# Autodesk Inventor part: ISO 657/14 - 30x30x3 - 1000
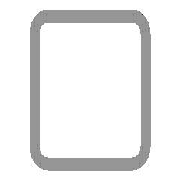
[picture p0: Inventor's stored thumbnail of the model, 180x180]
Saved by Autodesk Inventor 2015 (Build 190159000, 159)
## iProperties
IsCustomPart: 1
Created: 2014-02
Part Number: ISO 657/14 - 30x30x3 - 1000
Material: Steel, Mild
Description: Hot-rolled steel sections - part 14: hot-finished structrual hollow sections - Dimensions and sectional properties
Document SubType Name: Modeling
Standard: ISO
Designer: 徐冠倫
Standard Revision: Third edition 2000-03-15
Standards Organization: ISO
Language: en-US
Size Designation: 30x30x3
Categories: <MemberInstance><Categories><Category DisplayName="Structural Shapes" InternalName="089c4875-fa83-4c05-b084-43b9cc11f5ed" Mnemonic="GRDR"><CategoryParameter Dis
Stock Number: 30x30x3
Density: 7.85 g/cm^3
Appearance: Semi-Polished
Mass: 2422.11 g
Surface Area: 2063.16 cm^2
Volume: 308.549 cm^3
_CCFamilyMember: 8
_CCFamilyDisplayName: ISO 657/14 - 2000 (Square) - Hot-rolled steel sections - part 14: hot-finished structrual hollow sections - Dimensions and sectional properties
_FrameMemberDoc: Frame Member File
_Version: 15.0.0
_GetPNFromCC: 1
G_L: 1000.000 mm
G_W: 30.000 mm
G_H: 30.000 mm
Author: 徐冠倫
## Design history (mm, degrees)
node "Start plane"
node "End plane"
sketch "Sketch"
  geometry: L1 (-15, -10.5)-(-15, 10.5); L2 (-10.5, 15)-(10.5, 15); L3 (15, 10.5)-(15, -10.5); L4 (10.5, -15)-(-10.5, -15); L5 (-10.5, 12)-(10.5, 12); L6 (12, 10.5)-(12, -10.5); L7 (10.5, -12)-(-10.5, -12); L8 (-12, -10.5)-(-12, 10.5); L9 (0, 22.305)-(0, -22.305) reference; L10 (-22.305, 0)-(22.305, 0) reference; A1 r 4.5 centre (-10.5, -10.5) between (-15, -10.5) and (-10.5, -15); A2 r 4.5 centre (-10.5, 10.5) between (-10.5, 15) and (-15, 10.5); A3 r 4.5 centre (10.5, 10.5) between (15, 10.5) and (10.5, 15); A4 r 4.5 centre (10.5, -10.5) between (10.5, -15) and (15, -10.5); A5 r 1.5 centre (-10.5, 10.5) between (-10.5, 12) and (-12, 10.5); A6 r 1.5 centre (10.5, 10.5) between (12, 10.5) and (10.5, 12); A7 r 1.5 centre (10.5, -10.5) between (10.5, -12) and (12, -10.5); A8 r 1.5 centre (-10.5, -10.5) between (-12, -10.5) and (-10.5, -12)
  constraints: 16 end point, 16 point on circle, 8 centre point, 8 tangent, 4 parallel, 3 equal radius, 2 perpendicular, 7 other
  dimensions: "d7" = 4.5 radius of A1 (= G_IR); "d10" = 30 distance between parallel lines of L2 L4 (= G_H); "d11" = 30 distance between parallel lines of L1 L3 (= G_W); "d12" = 3 distance between parallel lines of L3 L6 (= G_T); "d15" = 15 distance between parallel lines of L2 L10 (= 0.5 x d10); "d16" = 15 distance between parallel lines of L9 L3 (= 0.5 x d11)
extrude "Body" new body sketch "Sketch" stored distance "d3" = 1000 (= G_L); taper "d4" = 0 deg
node "Driven Length"
  sketch "Sketch3"
    geometry: L1 (0, 0)-(10, 0) reference
    constraints: 2 end point, 1 horizontal
  workplane "Work Plane3"
  sketch "Sketch4"
    geometry: L1 (-2, 0)-(12, 0) reference; L2 (-2, 1000)-(12, 1000) reference
    dimensions: "d18" = 1000 distance between parallel lines of L1 L2 (derived)
body "Solid1"
other parameters: "G_W" = 30 [user parameter; used in 1 equation term], "G_H" = 30 [user parameter; used in 1 equation term], "G_T" = 3 [user parameter; used in 1 equation term], "G_IR" = 4.5 [user parameter; used in 1 equation term], "G_L" = 1000 (= d18) [user parameter; used in 1 equation term], "G_OFFSET_START" = 0 [user parameter; used in 1 equation term], "G_OFFSET_END" = 0 [user parameter; used in 1 equation term], "d13" = 0 (computed from G_OFFSET_START), "d17" = 90 deg
